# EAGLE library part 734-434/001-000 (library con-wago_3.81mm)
Serie 734, Doppelstock-Stiftleisten Einlötstift abgewinkelt 1 x 1 mm / Series 734, Double-deck male headers Angled solder pin 1 x 1 mm Polzahl / Pole No.: 4 Rastermaß / Pitch: 3.81 mm Bemessungsspannung / Rated Voltage: 160 V Nennstrom / Nominal Current: 10 A Lötstiftlänge: / Solder Pin Length: 3.6 mm Farbe / Color: orange / orange Stand: 01.01.2012. Die jeweils aktuellen Daten zu diesem Artikel finden Sie in unserem Produktkatalog, den Sie unter www.wago.com einsehen können. As of: 01/01/2012. Please find the newest data for this article in our product catalogue, which can be viewed under www.wago.com.
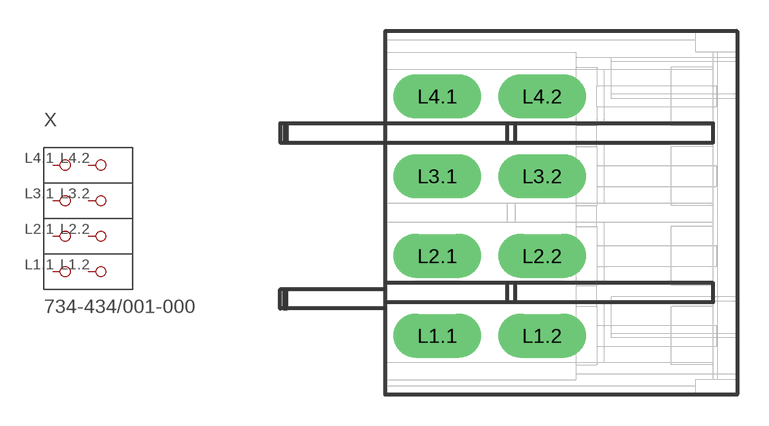
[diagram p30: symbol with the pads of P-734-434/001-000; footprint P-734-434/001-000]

Designator prefix X

## 734-434/001-000  [P-734-434/001-000]
L1.1  P1.1
L1.2  P1.2
L2.1  P2.1
L2.2  P2.2
L3.1  P3.1
L3.2  P3.2
L4.1  P4.1
L4.2  P4.2

## Footprint P-734-434/001-000 (pad centres in mm)
drill 1.4 long: L1.1 -3.4,-5.865; L1.2 1.6,-5.865; L2.1 -3.4,-2.055; L2.2 1.6,-2.055; L3.1 -3.4,1.755; L3.2 1.6,1.755; L4.1 -3.4,5.565; L4.2 1.6,5.565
